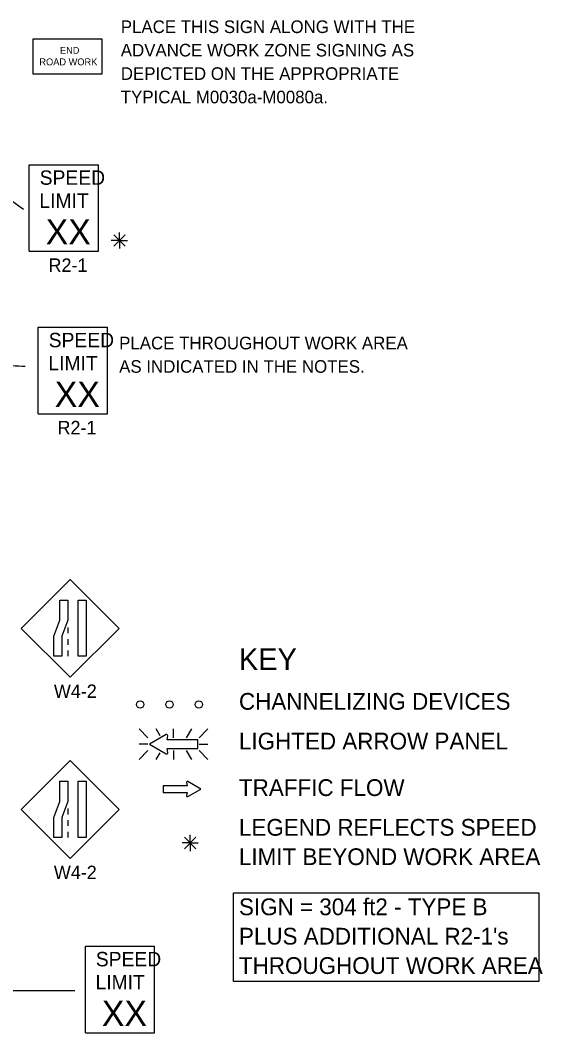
# Model space of a CAD drawing. Extents: x 16734 to 18475, y 5704 to 7011.
# Drawn here: x 17130 to 17420, y 6338 to 6900 of the extents above; entities that cross this region are included whole.
import ezdxf

# ---------------------------------------------------------------- set-up
doc = ezdxf.new("R2010")
doc.units = 0
for name, color, linetype in [('MT_SCRATCH_LEVEL_E', 7, 'Continuous'), ('TRAFFIC_SIGNS_PR', 7, 'Continuous'), ('TYPICAL_TEXT_DIMEN_EX', 7, 'Continuous'), ('TYPICAL_TEXT_DIMEN_PR', 7, 'Continuous')]:
    doc.layers.add(name, color=color, linetype=linetype)

msp = doc.modelspace()

# ---------------------------------------------------------------- linework, layer by layer
at = {"layer": 'MT_SCRATCH_LEVEL_E'}
for p, q in [((17222.24, 6475.4), (17208.99, 6475.4)), ((17208.99, 6475.4), (17208.99, 6471.65)), ((17222.24, 6475.4), (17208.99, 6475.4)), ((17208.99, 6475.4), (17208.99, 6471.65)), ((17221.93, 6477.17), (17222.24, 6475.4)), ((17221.93, 6477.17), (17222.24, 6475.4)), ((17229.85, 6473.55), (17222.61, 6477.65)), ((17229.85, 6473.55), (17222.61, 6477.65)), ((17222.61, 6469.4), (17229.85, 6473.55)), ((17222.61, 6469.4), (17229.85, 6473.55)), ((17208.99, 6471.65), (17222.24, 6471.65)), ((17208.99, 6471.65), (17222.24, 6471.65)), ((17222.24, 6471.65), (17221.93, 6469.88)), ((17222.24, 6471.65), (17221.93, 6469.88))]:
    msp.add_line(p, q, dxfattribs=at)
for centre, start, end in [((17222.39, 6477.25), 60.4248, 189.9638), ((17222.39, 6477.25), 60.4248, 189.9638), ((17222.39, 6469.81), 170.0362, 299.7731), ((17222.39, 6469.81), 170.0362, 299.7731)]:
    msp.add_arc(centre, 0.463, start, end, dxfattribs=at)
at = {"layer": 'TRAFFIC_SIGNS_PR'}
for p, q in [((17134.73, 6819.97), (17173.13, 6819.97)), ((17134.73, 6771.97), (17134.73, 6819.97)), ((17173.13, 6771.97), (17173.13, 6819.97)), ((17134.73, 6771.97), (17173.13, 6771.97)), ((17139.74, 6729.82), (17178.14, 6729.82)), ((17139.74, 6681.82), (17139.74, 6729.82)), ((17178.14, 6681.82), (17178.14, 6729.82)), ((17139.74, 6681.82), (17178.14, 6681.82)), ((17157.43, 6589.85), (17130.28, 6562.69)), ((17184.59, 6562.69), (17157.43, 6589.85)), ((17130.28, 6562.69), (17157.43, 6535.54)), ((17156.19, 6563.18), (17156.19, 6559.98)), ((17157.43, 6535.54), (17184.59, 6562.69)), ((17156.19, 6556.78), (17156.19, 6553.58)), ((17156.19, 6550.38), (17156.19, 6547.18)), ((17195.66, 6506.93), (17200.6, 6502)), ((17207.43, 6503.11), (17205.22, 6506.93)), ((17214.75, 6502), (17214.75, 6506.93)), ((17221.98, 6502), (17224.83, 6506.93)), ((17228.9, 6502), (17233.83, 6506.93)), ((17200.6, 6498.44), (17195.66, 6498.44)), ((17195.66, 6489.95), (17200.6, 6494.88)), ((17214.75, 6494.88), (17214.75, 6489.95)), ((17224.88, 6489.95), (17222.03, 6494.88)), ((17228.9, 6498.44), (17233.83, 6498.44)), ((17228.9, 6494.88), (17233.83, 6489.95)), ((17157.42, 6489.31), (17130.26, 6462.16)), ((17184.57, 6462.16), (17157.42, 6489.31)), ((17205.17, 6489.95), (17207.29, 6493.61)), ((17130.26, 6462.16), (17157.42, 6435)), ((17156.17, 6462.65), (17156.17, 6459.45)), ((17157.42, 6435), (17184.57, 6462.16)), ((17156.17, 6456.25), (17156.17, 6453.05)), ((17156.17, 6449.85), (17156.17, 6446.65)), ((17165.89, 6386.3), (17204.29, 6386.3)), ((17165.89, 6338.3), (17165.89, 6386.3)), ((17204.29, 6338.3), (17204.29, 6386.3)), ((17165.89, 6338.3), (17204.29, 6338.3))]:
    msp.add_line(p, q, dxfattribs=at)
for points in [[(17136.73, 6870.39), (17175.13, 6870.39), (17175.13, 6889.59), (17136.73, 6889.59)], [(17156.19, 6578.43), (17156.19, 6567.25), (17152.84, 6558.37), (17152.84, 6547.18), (17148.35, 6547.18), (17148.35, 6558.37), (17151.69, 6567.25), (17151.69, 6578.43)], [(17166.32, 6578.43), (17166.32, 6547.18), (17161.83, 6547.18), (17161.83, 6578.43)], [(17156.17, 6477.89), (17156.17, 6466.71), (17152.83, 6457.83), (17152.83, 6446.65), (17148.33, 6446.65), (17148.33, 6457.83), (17151.68, 6466.71), (17151.68, 6477.89)], [(17166.31, 6477.89), (17166.31, 6446.65), (17161.81, 6446.65), (17161.81, 6477.89)]]:
    msp.add_lwpolyline(points, close=True, dxfattribs=at)
for points in [[(17210.67, 6503.72), (17201.38, 6498.44), (17210.68, 6493.12)], [(17211.55, 6493.75), (17211.15, 6496.01), (17228.16, 6496.01), (17228.16, 6500.82), (17211.15, 6500.82), (17211.55, 6503.1)]]:
    msp.add_lwpolyline(points, dxfattribs=at)
for centre in [(17196.23, 6520.47), (17212.53, 6520.47), (17228.83, 6520.47)]:
    msp.add_circle(centre, 2, dxfattribs=at)
for centre, radius, start, end in [((17210.96, 6503.19), 0.598, 350.7308, 118.8916), ((17210.96, 6493.64), 0.597, 241.4833, 9.9593)]:
    msp.add_arc(centre, radius, start, end, dxfattribs=at)
at = {"layer": 'TYPICAL_TEXT_DIMEN_EX'}
msp.add_lwpolyline([(17248.05, 6415.94), (17417.51, 6415.94), (17417.51, 6366.74), (17248.05, 6366.74)], close=True, dxfattribs=at)
at = {"layer": 'TYPICAL_TEXT_DIMEN_PR'}
for p, q in [((17072.85, 6837.3), (17131.52, 6795.24)), ((17184.77, 6777.92), (17184.77, 6782.37)), ((17184.77, 6777.92), (17180.24, 6777.92)), ((17187.96, 6781.1), (17181.58, 6774.73)), ((17181.59, 6781.1), (17187.96, 6774.73)), ((17184.77, 6777.92), (17187.96, 6777.92)), ((17184.77, 6777.92), (17189.25, 6777.92)), ((17184.77, 6777.92), (17184.77, 6773.42)), ((17227.19, 6446.79), (17220.81, 6440.41)), ((17220.82, 6446.79), (17227.19, 6440.41)), ((17224, 6443.6), (17224, 6448.06)), ((17224, 6443.6), (17219.47, 6443.6)), ((17224, 6443.6), (17227.19, 6443.6)), ((17224, 6443.6), (17228.48, 6443.6)), ((17224, 6443.6), (17224, 6439.1)), ((17160.01, 6361.65), (17046.85, 6361.65))]:
    msp.add_line(p, q, dxfattribs=at)
msp.add_open_spline([(17076.4, 6730.03), (17124.86, 6730.03), (17124.86, 6719.28), (17089.95, 6719.28), (17089.95, 6710.23), (17124.15, 6708.46), (17132.44, 6708.17)], degree=3, dxfattribs=at)

# ---------------------------------------------------------------- texts
at = {"layer": 'TRAFFIC_SIGNS_PR'}
for s, height, p in [('PLACE THIS SIGN ALONG WITH THE', 7, (17185.5, 6893.04)), ('END', 3.831, (17151.73, 6881.52)), ('ADVANCE WORK ZONE SIGNING AS', 7, (17185.5, 6880.04)), ('ROAD WORK', 3.831, (17140.34, 6875.14)), ('DEPICTED ON THE APPROPRIATE', 7, (17185.5, 6867.04)), ('TYPICAL M0030a-M0080a.', 7, (17185.5, 6854.04)), ('SPEED', 8, (17140.5, 6808.83)), ('LIMIT', 8, (17140.34, 6796.03)), ('XX', 14.031, (17143.84, 6775.73)), ('R2-1', 7.44, (17145.41, 6760.53)), ('SPEED', 8, (17145.5, 6718.68)), ('PLACE THROUGHOUT WORK AREA', 7, (17184.58, 6717.52)), ('LIMIT', 8, (17145.34, 6705.88)), ('AS INDICATED IN THE NOTES.', 7, (17184.58, 6704.52)), ('XX', 14.031, (17148.85, 6685.58)), ('R2-1', 7.44, (17150.41, 6670.38)), ('W4-2', 7.44, (17148.39, 6524.1)), ('W4-2', 7.44, (17148.37, 6423.57)), ('SPEED', 8, (17171.65, 6375.16)), ('LIMIT', 8, (17171.49, 6362.36)), ('XX', 14.031, (17175, 6342.06))]:
    msp.add_text(s, height=height, dxfattribs=at).set_placement(p)
at = {"layer": 'TYPICAL_TEXT_DIMEN_EX'}
for s, height, p in [('KEY', 12, (17251.07, 6539.58)), ('CHANNELIZING DEVICES', 9.3, (17251.07, 6517.53)), ('LIGHTED ARROW PANEL', 9.3, (17251.07, 6495.48)), ('TRAFFIC FLOW', 9.3, (17251.07, 6469.68)), ('LEGEND REFLECTS SPEED', 9.3, (17251.07, 6447.63)), ('LIMIT BEYOND WORK AREA', 9.3, (17251.07, 6431.33)), ('SIGN = 304 ft2 - TYPE B', 9.3, (17251.07, 6403.53)), ("PLUS ADDITIONAL R2-1's", 9.3, (17251.07, 6387.23)), ('THROUGHOUT WORK AREA', 9.3, (17251.07, 6370.93))]:
    msp.add_text(s, height=height, dxfattribs=at).set_placement(p)

doc.saveas('drawing.dxf')
